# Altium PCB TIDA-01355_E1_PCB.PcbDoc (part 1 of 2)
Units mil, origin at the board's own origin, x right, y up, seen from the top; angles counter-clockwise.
Board outline 2150 x 1600 mil, 4 copper layers (Top Layer, GND, PWR, Bottom Layer), stack 59.906 mil thick; 85 components, 55 nets, 272 pads, 126 vias.
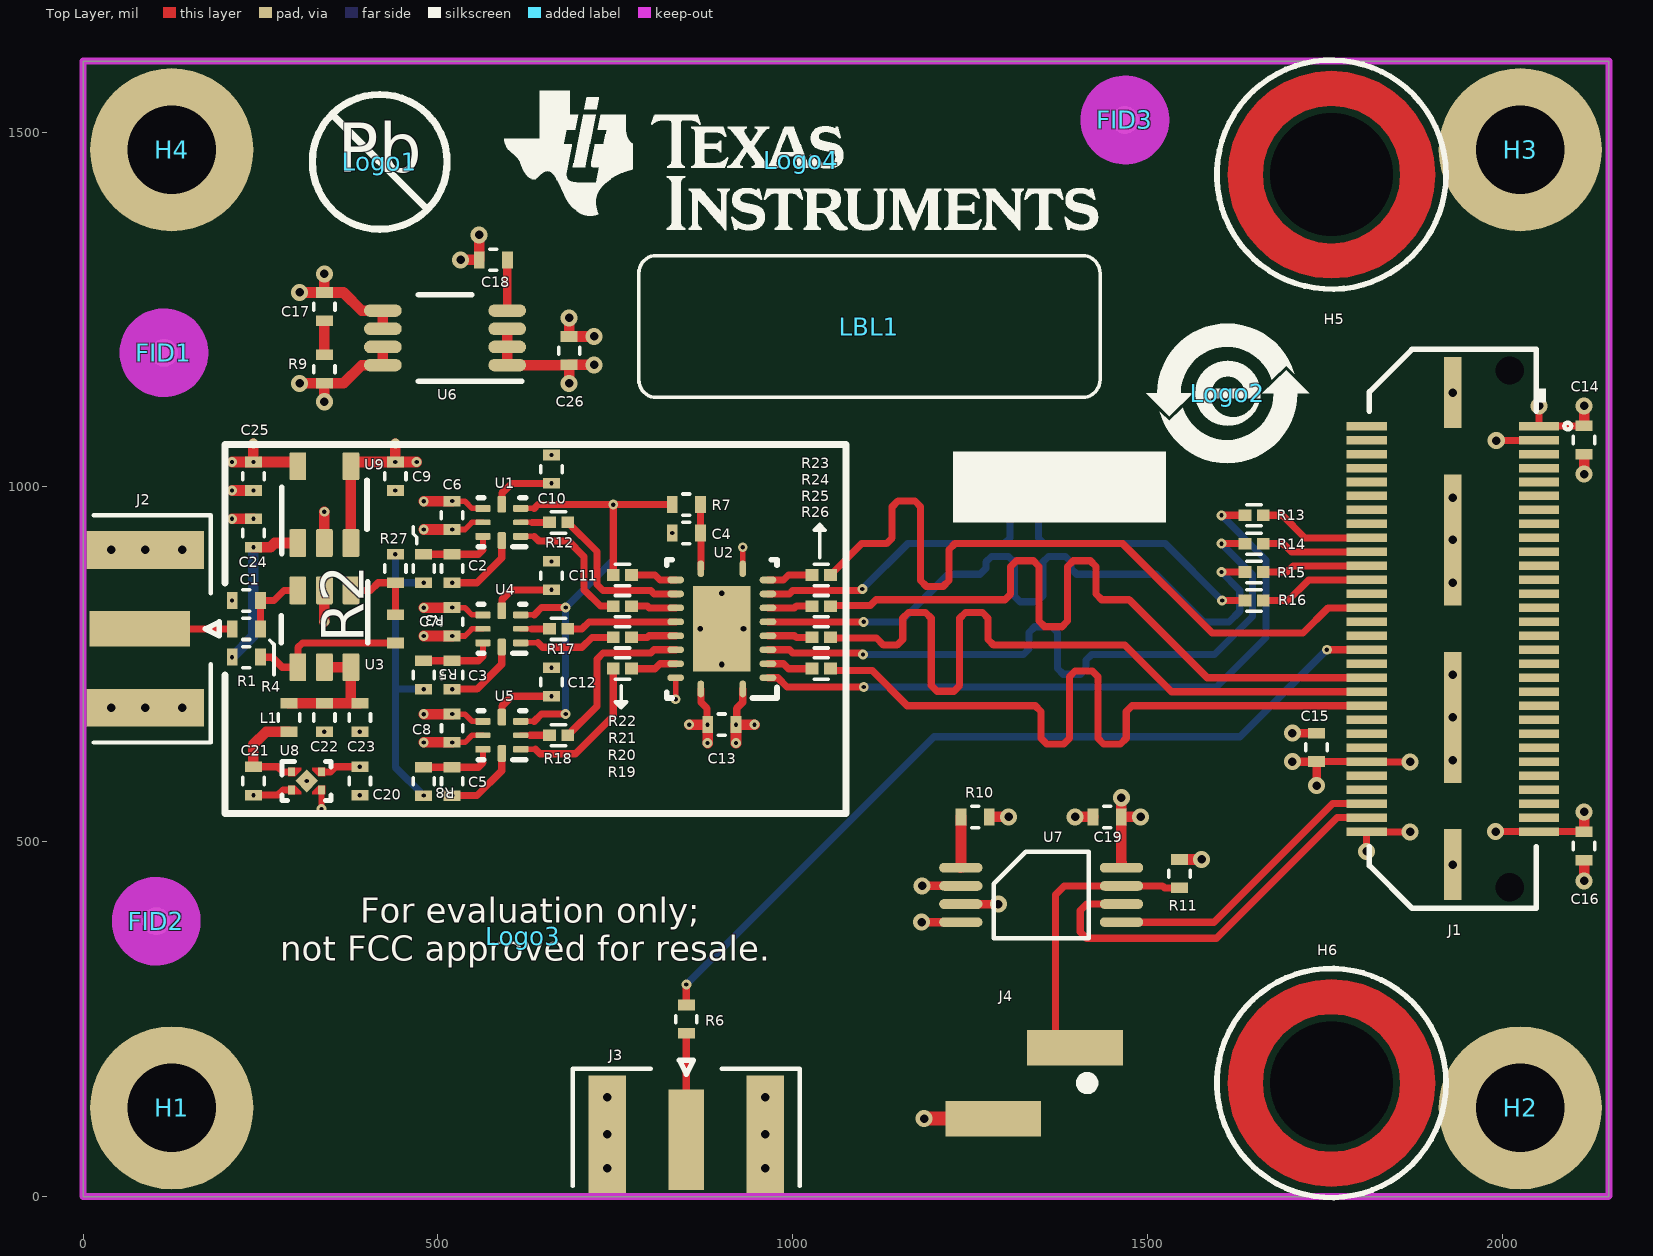
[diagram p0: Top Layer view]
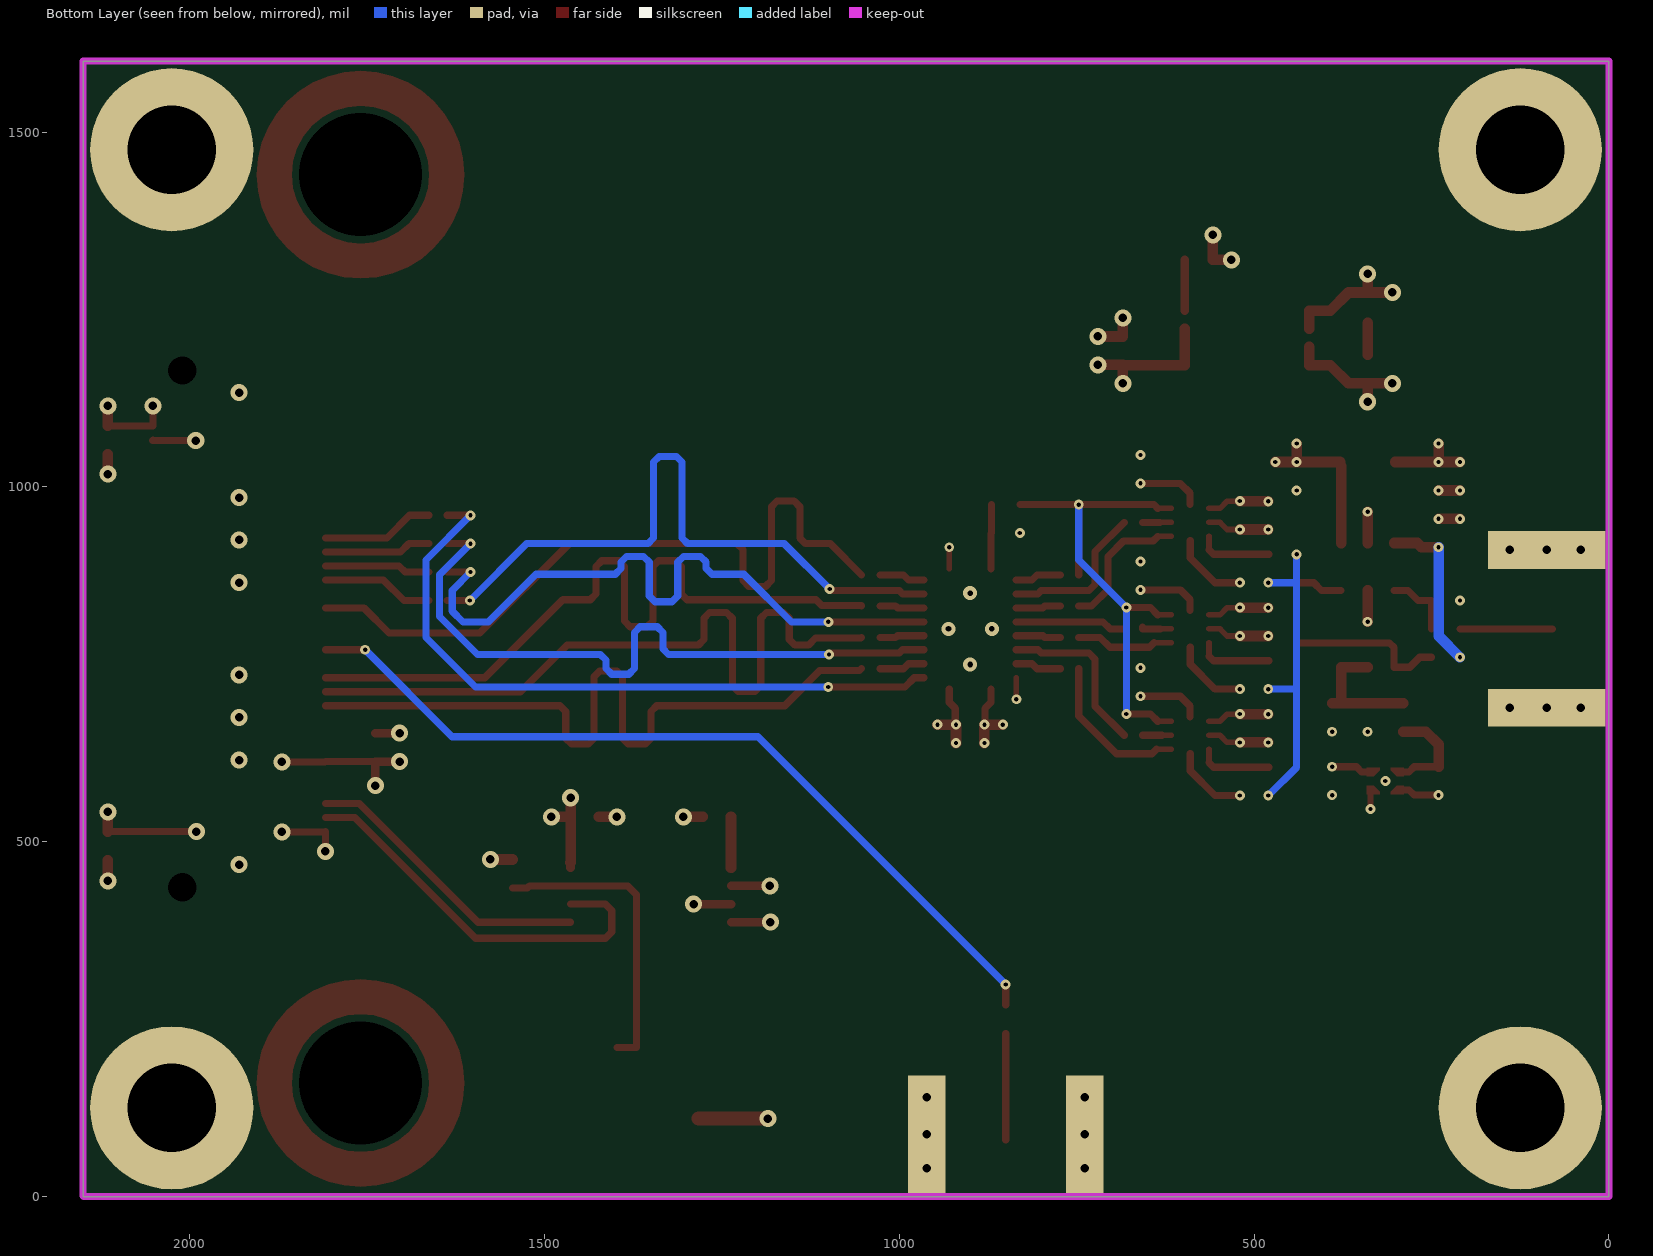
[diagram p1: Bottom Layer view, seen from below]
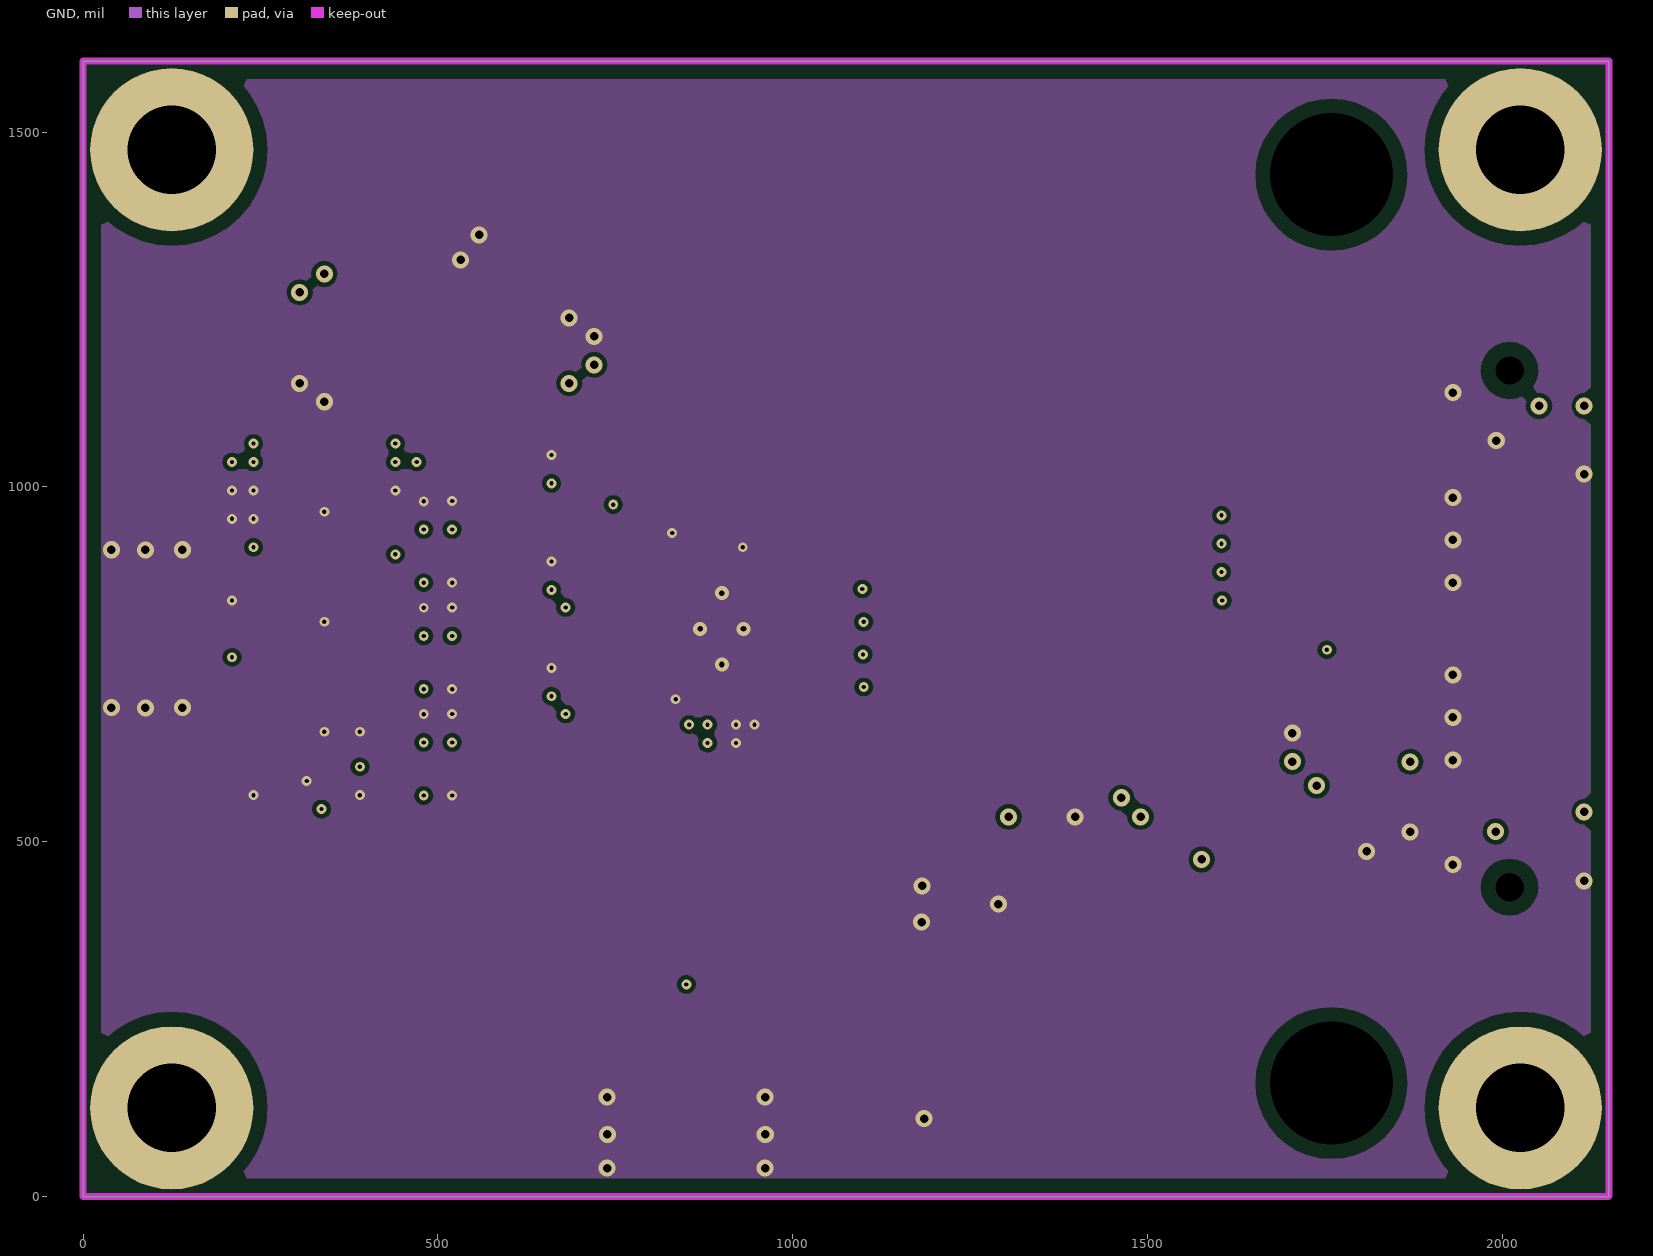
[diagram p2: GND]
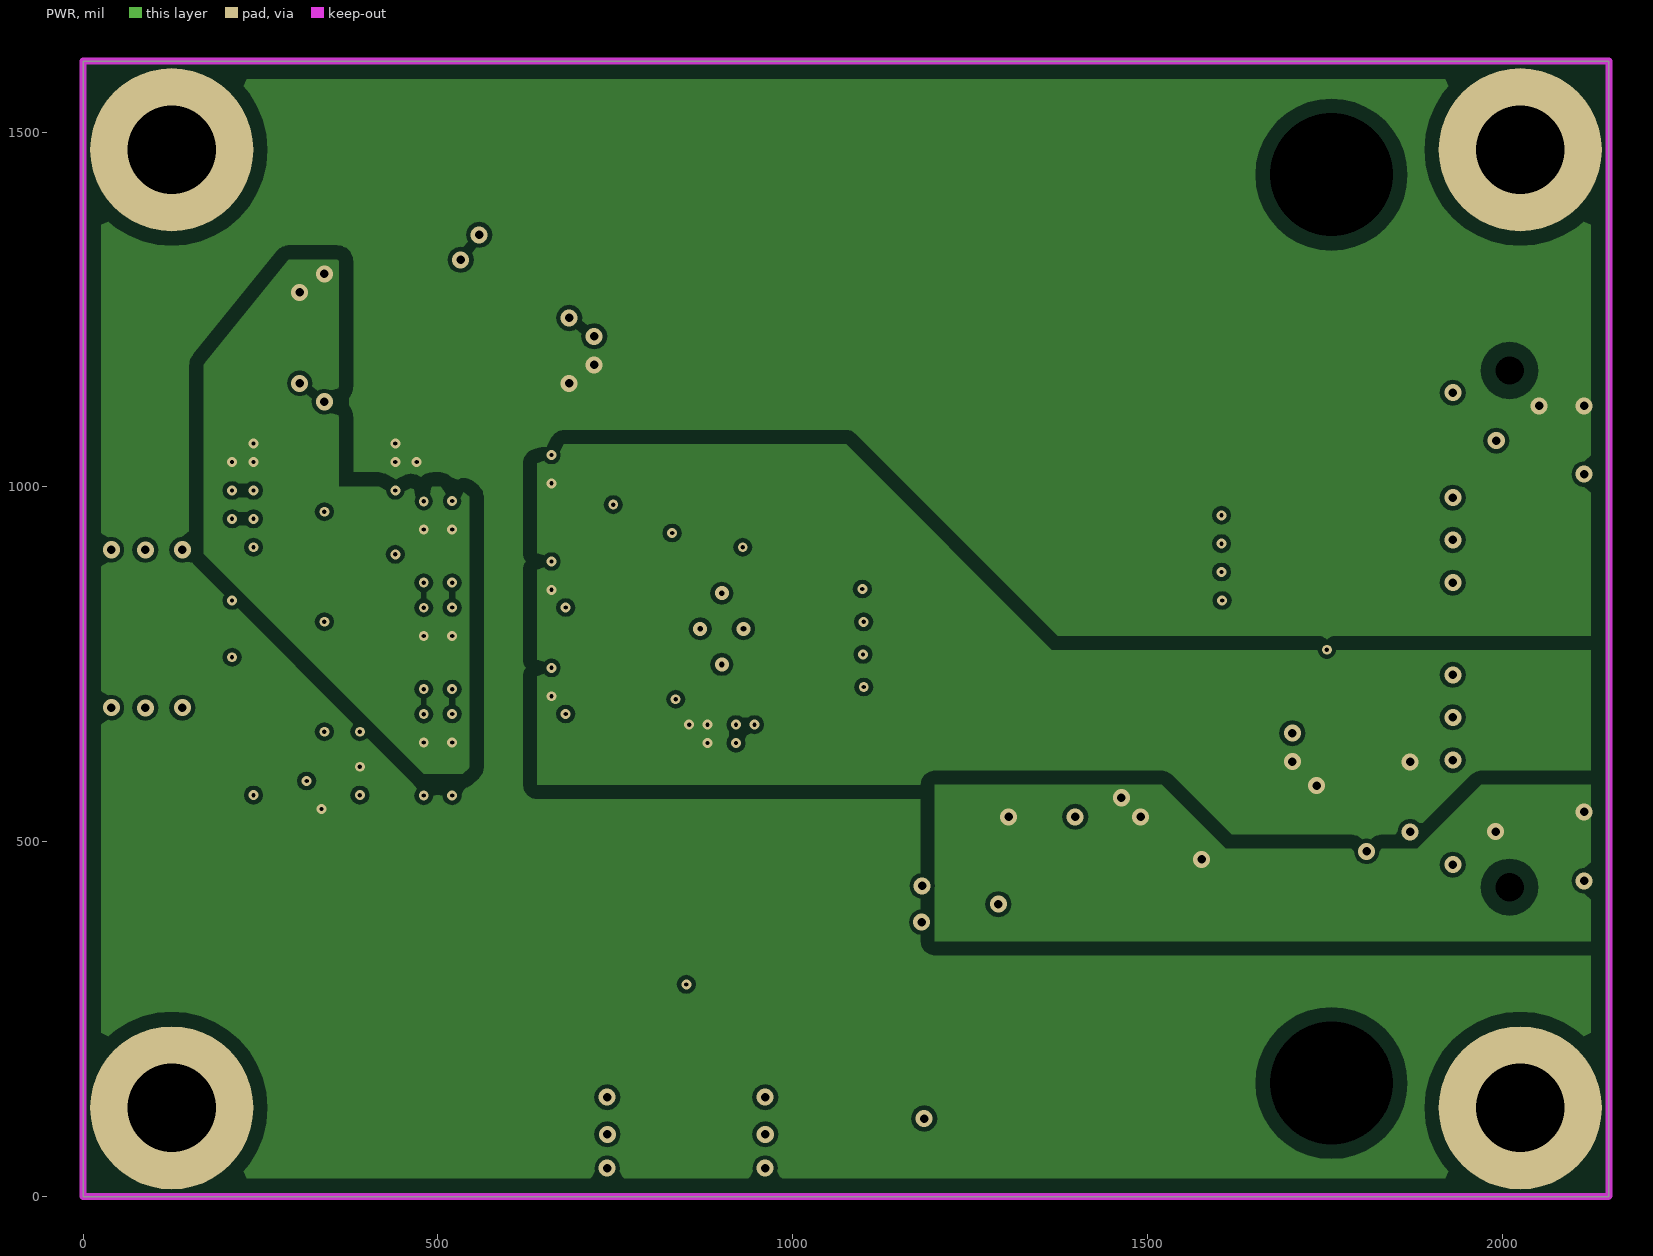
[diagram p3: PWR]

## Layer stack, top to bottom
Top Solder: solder mask 0.4, Solder Resist, Dk 3.5
Top Layer: signal copper 2.59
Dielectric1: core 6.3, FR-4, Dk 4.2
GND: signal copper 1.378
Dielectric 3: prepreg 39.37, Dk 4.2
PWR: signal copper 1.378
Dielectric 2: core 6.3, FR-4, Dk 4.2
Bottom Layer: signal copper 2.59
Bottom Solder: solder mask 0.4, Solder Resist, Dk 3.5

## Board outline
0,0 0,1600 2150,1600 2150,0

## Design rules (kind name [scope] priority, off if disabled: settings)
AcuteAngle [All] p1: minimum=4.50000000000000E+0001 checktracksonly=FALSE
AssemblyTestPointUsage [All] p1: valid=2
BoardOutlineClearance BoardOutlineClearance_MountingHoles [OnCopper and InComponentClass('Mounting Holes')] p1: gap=40
BoardOutlineClearance BoardOutlineClearance_Poly [OnCopper and IsPoly] p2: gap=25
BoardOutlineClearance [OnCopper and Not InComponentClass('Logo') and not InComponentClass('FiducialMark') and not InRegion(1000,500,4000,800) and not InPoly] p3: gap=75
Clearance Clearance_Keepouts [((IsTrack Or IsArc) And Not InPoly) And IsFree and IsKeepOut vs ((IsTrack Or IsArc) And Not InPoly) And IsFree and IsKeepOut] p1: gap=0
Clearance Clearance_Poly [InPolygon] p2: gap=20 except(6: Via-Poly; 8: SMDPad-Poly; 10: Arc-Poly Track-Poly)
Clearance [All] p3: gap=7.5
ComponentClearance ComponentClearance_MountingHoles_FiducialMarks [InComponentClass('Mounting Holes') vs InComponentClass('FiducialMark')] p1: gap=10 collisioncheckmode=3 verticalgap=10 showdistances=FALSE
ComponentClearance ComponentClearance_Shunt [InComponentClass('Header') vs InComponentClass('Shunt')] p2: gap=0 collisioncheckmode=3 verticalgap=0 showdistances=FALSE
ComponentClearance ComponentClearance_Logo [InComponentClass('Logo')] p3: gap=10 collisioncheckmode=3 verticalgap=10 showdistances=FALSE
ComponentClearance ComponentClearance_ScrewToNut [(HasFootprint('NY PMS 440 0025 PH')) vs (HasFootprint('Keystone_1902C'))] p4: gap=5 collisioncheckmode=3 verticalgap=10 showdistances=FALSE
ComponentClearance ComponentClearance_MountingHoles [InComponentClass('Mounting Holes')] p5: gap=100 collisioncheckmode=3 verticalgap=100000 showdistances=FALSE
ComponentClearance ComponentClearance_SmallPassives [HasFootprint('0201*') or HasFootprint('0402*') or HasFootprint('0508') or HasFootprint('0603*') or HasFootprint('0612') or HasFootprint('0805*') or HasFootprint('0815*') or HasFootprint('0830*') or HasFootprint('1206*') or HasFootprint('1210*') or HasFootprint('1808*') or HasFootprint('1812*') or HasFootprint('1825*') or HasFootprint('2010*') or HasFootprint('2220*') or HasFootprint('2225*') or HasFootprint('2512*') or HasFootprint('2728*') or HasFootprint('3518*') vs HasFootprint('0201*') or HasFootprint('0402*') or HasFootprint('0508') or HasFootprint('0603*') or HasFootprint('0612') or HasFootprint('0805*') or HasFootprint('0815*') or HasFootprint('0830*') or HasFootprint('1206*') or HasFootprint('1210*') or HasFootprint('1808*') or HasFootprint('1812*') or HasFootprint('1825*') or HasFootprint('2010*') or HasFootprint('2220*') or HasFootprint('2225*') or HasFootprint('2512*') or HasFootprint('2728*') or HasFootprint('3518*')] p6: gap=12 collisioncheckmode=3 verticalgap=10 showdistances=FALSE
ComponentClearance ComponentClearance_THtoSMT [IsThruComponent vs IsSMTComponent] p7: gap=20 collisioncheckmode=3 verticalgap=15 showdistances=FALSE
ComponentClearance ComponentClearance_THtoTH [IsThruComponent vs IsThruComponent] p8: gap=20 collisioncheckmode=3 verticalgap=20 showdistances=FALSE
ComponentClearance [All] p9: gap=20 collisioncheckmode=3 verticalgap=10 showdistances=FALSE
DiffPairsRouting [All] p1: maxlimit=100 minlimit=10 mostfreqgap=10 toplayer_minwidth=15 toplayer_maxwidth=15 toplayer_prefwidth=15 midlayer1_minwidth=15 midlayer1_maxwidth=15 midlayer1_prefwidth=15 midlayer2_minwidth=15 midlayer2_maxwidth=15 midlayer2_prefwidth=15 bottomlayer_minwidth=15 bottomlayer_maxwidth=15 bottomlayer_prefwidth=15 maxuncoupledlength=1000
FabricationTestPointUsage TestPointUsage [All] p1: valid=2 allowmultiple=FALSE
FabricationTestpoint Testpoint [All] p1: side=3 testpointundercomponent=TRUE minsize=40 maxsize=100 preferedsize=60 minholesize=0 maxholesize=40 preferedholesize=32 testpointgrid=1 allowsidetop=TRUE allowsidebottom=TRUE usegrid=TRUE gridtolerance=0.01
FanoutControl Fanout_LCC [IsLCC] p1: bgadir=Out bgaviamode=Centered fanoutstyle=Auto fanoutdirection=Alternating viagrid=1 // Fanout_LCC (Default Rule)
FanoutControl Fanout_BGA [IsBGA] p2: bgadir=Out bgaviamode=Centered fanoutstyle=Auto fanoutdirection=Alternating viagrid=1 // Fanout_BGA (Default Rule)
FanoutControl Fanout_Default [All] p4: bgadir=Out bgaviamode=Centered fanoutstyle=Auto fanoutdirection=Alternating viagrid=1 // Fanout_Default (Default Rule)
FanoutControl Fanout_Small [(CompPinCount < 5)] p5: bgadir=Out bgaviamode=Centered fanoutstyle=Auto fanoutdirection=OutThenIn viagrid=1 // Fanout_Small (Default Rule)
HoleSize [All] p1: absolutevalues=TRUE maxlimit=251 minlimit=6 maxpercent=80.000 minpercent=20.000
MinimumAnnularRing MinimumAnnularRing_ThermalPadVias [IsVia and InAnyComponent] p1: minimumring=3
MinimumAnnularRing [All] p2: minimumring=3
MinimumSolderMaskSliver MinimumSolderMaskSliver_Logo [InComponentClass('Logo') vs InComponentClass('Logo')] p1: minsoldermaskwidth=0.7
MinimumSolderMaskSliver [All] p2: minsoldermaskwidth=3
PlaneConnect [All] p1: planeconnectstyle=Direct reliefexpansion=10 reliefentries=4 reliefconductorwidth=10 reliefairgap=10
PolygonConnect [All] p1: connectstyle=Direct reliefconductorwidth=10 reliefentries=4 polygonreliefangle="90 Angle" airgapwidth=10
RoutingVias ThermalPadVias [IsVia and InAnyComponent] p1: holewidth=7.87 width=19.68 viastyle="Through Hole" minholewidth=7.87 minwidth=19.68 maxholewidth=12.99 maxwidth=23.62
RoutingVias [All] p2: holewidth=12 width=24 viastyle="Through Hole" minholewidth=6 minwidth=14 maxholewidth=16 maxwidth=32
SilkToBoardRegionClearance [Not ((IsComment or IsDesignator) And (Hide <> 'False')) and not InRegion(1000,500,4000,800)] p1:
SilkToSilkClearance SilkToSilkClearance_Pb-FreeLogo [(HasFootprint('Pb-Free_Overlay_Medium') OR HasFootprint('Pb-Free_Overlay_Small')) vs (HasFootprint('Pb-Free_Overlay_Medium') OR HasFootprint('Pb-Free_Overlay_Small'))] p1: silktosilkclearance=0
SilkToSilkClearance [All] p2: silktosilkclearance=0
SilkToSolderMaskClearance SilkToComponentPadClearance [IsPad and InAnycomponent] p1: minsilkscreentomaskgap=0 clearancetoexposedcopper=TRUE
SilkToSolderMaskClearance "Silk to Solder Mask Opening" [All] p2: minsilkscreentomaskgap=0 clearancetoexposedcopper=FALSE
SolderMaskExpansion [All] p1: expansion=1.97
Width Width_PWR [InNetClass('PWR')] p1: maxlimit=30 minlimit=6 preferedwidth=15
Width [All] p2: maxlimit=30 minlimit=6 preferedwidth=10.06 checkconnectedcopper=TRUE
15 further rules are at their usual default settings.

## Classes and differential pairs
component class Header: J4
component class TIDA-01355_E1_AFE_Circuit: C1 C2 C3 C4 C5 C6 C7 C8 C9 C10 C11 C12 C13 C14 C15 C16 C17 C18 C19 C20 C21 C22 C23 C24 C25 C26 J1 J2 J3 J4 L1 R1 R2 R3 R4 R5 R6 R7 R8 R9 R10 R11 R12 R13 R14 R15 R16 R17 R18 R19 R20 R21 R22 R23 R24 R25 R26 R27 U1 U2 U3 U4 U5 U6 U7 U8 U9
component class Logo: Logo4
component class TIDA-01355_E1_EVM_Hardware: FID1 FID2 FID3 H1 H2 H3 H4 H5 H6 LBL1 Logo1 Logo2 Logo3 Logo4 ZZ1 ZZ2 ZZ3 ZZ4
component class FiducialMark: FID1 FID2 FID3
component class AssemblyNote: ZZ1 ZZ2 ZZ3 ZZ4
component class Label: LBL1
net class AVDD: AVDD
net class EVM_DVDD: EVM_DVDD
net class EVM_REG_5V5: EVM_REG_5V5
net class EVM_ID_PWR: EVM_ID_PWR

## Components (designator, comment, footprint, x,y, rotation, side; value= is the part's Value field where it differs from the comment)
C1 "GRM1555C1H100JA01D" 0402S 230,840 r180 top
C2 "GRM1555C1E111JA01D" 0402S 520,885 r270 top
C3 "GRM1555C1E111JA01D" 0402S 520,735 r270 top
C4 "GRM1555C1E510JA01D" 0402S 850,935 r180 top
C5 "GRM1555C1E111JA01D" 0402S 520,585 r270 top
C6 "C1005X5R1C225K050BC" 0402S 520,960 r90 top
C7 "C1005X5R1C225K050BC" 0402S 520,810 r90 top
C8 "C1005X5R1C225K050BC" 0402S 520,660 r90 top
C9 "885012205037" 0402S 440,1015 r270 top
C10 "885012205037" 0402S 660,1025 r90 top
C11 "885012205037" 0402S 660,875 r90 top
C12 "885012205037" 0402S 660,725 r90 top
C13 "885012205037" 0402S 900,665 r0 top
C14 "CL05A106MP5NUNC" 0402S 2115,1066 r270 top
C15 "CL05A106MP5NUNC" 0402S 1738,633 r90 top
C16 "CL05A106MP5NUNC" 0402S 2115,494 r270 top
C17 "LDK105EBJ226MV-F" 0402_080S 340,1254 r270 top
C18 "GCM155C71A105KE38D" 0402_070 578,1320 r180 top
C19 "885012205037" 0402S 1443,535 r180 top
C20 "CL05A106MP5NUNC" 0402S 390,585.67 r270 top
C21 "CL05A106MP5NUNC" 0402S 240,585.67 r270 top
C22 "CL05A106MP5NUNC" 0402S 340,675 r270 top
C23 "885012205037" 0402S 390,675 r270 top
C24 "CL05A106MP5NUNC" 0402S 240,935 r90 top
C25 "CL05A106MP5NUNC" 0402S 240,1015 r270 top
C26 "885012205037" 0402S 685,1192 r90 top
FID1 "Fiducial" Fiducial10-30 114,1189 r0 top
FID2 "Fiducial" Fiducial10-30 103,388 r0 top
FID3 "Fiducial" Fiducial10-30 1468,1517 r0 top
H1 "PMSSS 440 0025 PH" B_F_PMSSS4400025PH 125,125 r0 top locked
H2 "PMSSS 440 0025 PH" B_F_PMSSS4400025PH 2025,125 r0 top locked
H3 "PMSSS 440 0025 PH" B_F_PMSSS4400025PH 2025,1475 r0 top locked
H4 "PMSSS 440 0025 PH" B_F_PMSSS4400025PH 125,1475 r0 top locked
H5 "9774050360R" Wurth_WA-SMSI 1759,1440 r0 top
H6 "9774050360R" Wurth_WA-SMSI 1759,160 r0 top
J1 "QTH-030-01-L-D-A" Samtec_QTH-030-01-x-D-A 1930,800 r270 top locked
J2 "SMA-J-P-H-ST-EM1" SAMTEC_SMA-J-P-H-ST-EM1 5,800 r270 top
J3 "SMA-J-P-H-ST-EM1" SAMTEC_SMA-J-P-H-ST-EM1 850,5 r0 top
J4 "TSM-102-01-L-SV" Samtec_TSM-102-01-L-SV 1340,160 r270 top
L1 "BLM15AX102SN1D" 0402S 290,675 r90 top
LBL1 "Size: 0.65\" x 0.20 \"" Label_650x200 1108,1226 r0 top
Logo1 "Pb-Free Symbol" Pb-Free_Overlay_Medium 418,1458 r0 top
Logo2 "China RoHS" ChinaRoHS_5mm 1613,1132 r0 top
Logo3 "FCC disclaimer" FCC_disclaimer_stacked 620,367 r0 top
Logo4 "Texas Instruments" TI_Stacked_Overlay_Small 1012,1460 r0 top
R1 "PCF0402-12-3K32BT1" 0402S 230,760 r0 top
R2 "CRCW04020000Z0ED" 0402S 440,800 r90 top
R3 "CRCW04020000Z0ED" 0402S 480,885 r270 top
R4 "CRCW0402150RJNED" 0402S 230,800 r0 top
R5 "CRCW04020000Z0ED" 0402S 480,735 r270 top
R6 "CRCW040210R0FKED" 0402S 850,250 r90 top
R7 "CRCW040220R0FKED" 0402S 850,975 r0 top
R8 "CRCW04020000Z0ED" 0402S 480,585 r270 top
R9 "CRCW04020000Z0ED" 0402S 340,1166 r90 top
R10 "ERJ-2GEJ103X" 0402S 1257,535 r0 top
R11 "ERJ-2GEJ103X" 0402S 1545,455 r90 top
R12 "ERJ-1GEF49R9C" 0201 670,950 r0 top
R13 "ERJ-1GEF49R9C" 0201 1650,960 r0 top
R14 "ERJ-1GEF49R9C" 0201 1650,920 r0 top
R15 "ERJ-1GEF49R9C" 0201 1650,880 r0 top
R16 "ERJ-1GEF49R9C" 0201 1650,840 r0 top
R17 "ERJ-1GEF49R9C" 0201 670,800 r0 top
R18 "ERJ-1GEF49R9C" 0201 670,650 r0 top
R19 "ERJ-1GEF49R9C" 0201 760,744 r0 top
R20 "ERJ-1GEF49R9C" 0201 760,788 r0 top
R21 "ERJ-1GEF49R9C" 0201 760,832 r0 top
R22 "ERJ-1GEF49R9C" 0201 760,876 r0 top
R23 "ERJ-1GEF49R9C" 0201 1040,876 r180 top
R24 "ERJ-1GEF49R9C" 0201 1040,832 r180 top
R25 "ERJ-1GEF49R9C" 0201 1040,788 r180 top
R26 "ERJ-1GEF49R9C" 0201 1040,744 r180 top
R27 "ERJ-2RKF33R0X" 0402S 440,885 r90 top
U1 "ADS7056IRUGR" RUG0008A 590,950 r180 top
U2 "SN74AUCH244RGYR" RGY0020A 900,800 r180 top
U3 "OPA836IDBVR" DBV0006A_N 340,800 r270 top
U4 "ADS7056IRUGR" RUG0008A 590,800 r180 top
U5 "ADS7056IRUGR" RUG0008A 590,650 r180 top
U6 "REF6030IDGKR" DGK0008A_N 510,1210 r180 top
U7 "BR24G32FVT-3AGE2" TSOP65P640X120-8N 1350,425 r0 top
U8 "LP5907SNX-4.5/NOPB" DQN0004A 315,585.67 r0 top
U9 "REF2033AIDDCR" DDC0005A_N 340,975 r90 top
ZZ1 "This Assembly Note is for PCB labels only" AssemblyNoteLabel 185,3938 r0 top
ZZ2 "These assemblies are ESD sensitive, ESD precautions shall be observed." AssemblyNote 185,3829.11 r0 top
ZZ3 "These assemblies must be clean and free from flux and all contaminants. Use of no clean flux is not acceptable." AssemblyNote 185,3740.56 r0 top
ZZ4 "These assemblies must comply with workmanship standards IPC-A-610 Class 2, unless otherwise specified." AssemblyNote 185,3652 r0 top

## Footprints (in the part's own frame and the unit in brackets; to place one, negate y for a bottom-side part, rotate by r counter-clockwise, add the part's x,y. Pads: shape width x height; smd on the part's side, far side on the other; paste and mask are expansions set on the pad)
0201 [mm] "Data from Kemet datasheet CC101_COM dated 7/28/11"
  rect 0.46x0.42 smd mask+0.048: 1(-0.33,0) 2(0.33,0)
  silkscreen extent -0.25,-0.38 0.25,0.38, body extent -0.31,-0.16 0.31,0.16, height 0.26
0402_070 [mil] "SMD, 2-Leads, Body 1.2x0.7mm, Height 0.7mm"
  rect 15x24 smd: 1(-20,0) 2(20,0)
  silkscreen extent -5,-15 5,15, body extent -24,-14 24,14, height 28
0402_080S [mil] "Based on C0402S footprint from PADS legacy"
  rect 15x24 smd: 1(-20,0) 2(20,0)
  silkscreen extent -5,-15 5,15, body extent -26,-16 26,16, height 31
0402S [mil] "Based on C0402S footprint from PADS legacy"
  rect 15x24 smd: 1(-20,0) 2(20,0)
  silkscreen extent -5,-15 5,15, body extent -22,-12 22,12, height 24
AssemblyNote [mil] "Assembly Note"
AssemblyNoteLabel [mil] "Assembly Note for PCB Labels"
B_F_PMSSS4400025PH [mil] "MACHINE SCREW PAN PHILLIPS 4-40"
  round 230 hole 125: 1(0,0)
  body extent -109,-109 110,110, height 79
ChinaRoHS_5mm [mil] "Minimum height for China RoHS symbol"
  silkscreen extent -115,-99 114,98
DBV0006A_N [mm] "SOT23, 6-Leads, Body 2.9x1.6mm, Pitch 0.95mm, Lead Span 2.8mm, IPC Medium Density"
  rrect17% 1x0.6 smd: 1(-1.375,0.95) 2(-1.375,0) 3(-1.375,-0.95) 4(1.375,-0.95) 5(1.375,0) 6(1.375,0.95)
  silkscreen extent -1.68,-1.55 0.5,1.55, body extent -1.42,-1.46 1.42,1.46, height 1.12
DDC0005A_N [mm]
  rrect17% 1x0.6 smd: 1(-1.375,0.95) 2(-1.375,0) 3(-1.375,-0.95) 4(1.375,-0.95) 5(1.375,0.95)
  silkscreen extent -1.75,-1.52 0.88,1.53, body extent -1.41,-1.45 1.41,1.45, height 1.1
DGK0008A_N [mm] "TSOP, 8-Leads, Body 3x3mm, Pitch 0.65mm, IPC Medium Density"
  oval 1.35x0.45 smd: 1(-2.225,0.975) 2(-2.225,0.325) 3(-2.225,-0.325) 4(-2.225,-0.975) 5(2.225,-0.975) 6(2.225,-0.325) 7(2.225,0.325) 8(2.225,0.975)
  silkscreen extent -2.75,-1.55 0.95,1.55, body extent -2.45,-1.5 2.45,1.5, height 0.96
DQN0004A [mm] "SON, 0.65mm pitch"
  rect 0.25x0.31 smd paste-1 mask-0.31: 1(-0.535,0.325) 2(-0.535,-0.325) 3(0.535,-0.325) 4(0.535,0.325)
  rect 0.58x0.58 smd rot 45 paste-0.065 mask-0.05: 5(0,0)
  Top Layer region: -0.66,-0.48 -0.2,-0.48 -0.2,-0.379 -0.409,-0.17 -0.66,-0.17
  Top Layer region: 0.66,-0.48 0.2,-0.48 0.2,-0.379 0.409,-0.17 0.66,-0.17
  Top Layer region: 0.66,0.48 0.2,0.48 0.2,0.379 0.409,0.17 0.66,0.17
  Top Layer region: -0.66,0.48 -0.2,0.48 -0.2,0.379 -0.409,0.17 -0.66,0.17
  silkscreen extent -0.88,-0.7 0.88,0.7, body extent -0.53,-0.53 0.53,0.53, height 0.42
FCC_disclaimer_stacked [mil]
Fiducial10-30 [mm]
  round 1 smd mask+1: 1(0,0)
  Top Layer keep-out circle w1.678: c0,0 r0.75
Label_650x200 [mil] "Thermal Transfer Label"
  silkscreen extent -325,-100 325,100, body extent -325,-100 325,100, height 1
Pb-Free_Overlay_Medium [mil]
  silkscreen extent -95,-95 95,95
RGY0020A [mm] "QFN, 20-Leads, Body 4.5x3.5mm, Pitch 0.5mm, Thermal Pad 3.05x2.05mm, TI Recommended"
  oval 0.24x0.6 smd: 1(-0.75,2.15) 10(-0.75,-2.15) 11(0.75,-2.15) 20(0.75,2.15)
  oval 0.6x0.24 smd: 2(-1.65,1.75) 3(-1.65,1.25) 4(-1.65,0.75) 5(-1.65,0.25) 6(-1.65,-0.25) 7(-1.65,-0.75) 8(-1.65,-1.25) 9(-1.65,-1.75) 12(1.65,-1.75) 13(1.65,-1.25) 14(1.65,-0.75) 15(1.65,-0.25) 16(1.65,0.25) 17(1.65,0.75) 18(1.65,1.25) 19(1.65,1.75)
  rect 2.05x3.05 smd paste-1.025: 21(0,0)
  silkscreen extent -1.97,-2.47 1.97,2.47, body extent -1.75,-2.25 1.75,2.25, height 1
RUG0008A [mm] "QFN, 8-Leads, Body 1.5x1.5mm, Pitch 0.5mm, TI Recommended"
  rrect40% 0.55x0.25 smd: 1(-0.675,0.5) 3(-0.675,-0.5) 5(0.675,-0.5) 7(0.675,0.5)
  rrect50% 0.55x0.2 smd: 2(-0.675,0) 6(0.675,0)
  rrect33% 0.3x0.6 smd: 4(0,-0.65) 8(0,0.65)
  silkscreen extent -0.85,-0.87 0.85,0.87, body extent -0.78,-0.78 0.77,0.77, height 0.41
Samtec_QTH-030-01-x-D-A [mil] "Header (Shrouded), 19.7mil, 30x2, SMT"
  rect 12x57 smd: 1(-285.7,121.5) 2(-285.7,-121.5) 3(-266,121.5) 4(-266,-121.5) 5(-246.3,121.5) 6(-246.3,-121.5) 7(-226.6,121.5) 8(-226.6,-121.5) 9(-206.9,121.5) 10(-206.9,-121.5) 11(-187.2,121.5) 12(-187.2,-121.5) 13(-167.5,121.5) 14(-167.5,-121.5) 15(-147.8,121.5) 16(-147.8,-121.5) 17(-128.1,121.5) 18(-128.1,-121.5) 19(-108.4,121.5) 20(-108.4,-121.5) 21(-88.7,121.5) 22(-88.7,-121.5) 23(-69,121.5) 24(-69,-121.5) 25(-49.3,121.5) 26(-49.3,-121.5) 27(-29.6,121.5) 28(-29.6,-121.5) 29(-9.9,121.5) 30(-9.9,-121.5) 31(9.8,121.5) 32(9.8,-121.5) 33(29.5,121.5) 34(29.5,-121.5) 35(49.2,121.5) 36(49.2,-121.5) 37(68.9,121.5) 38(68.9,-121.5) 39(88.6,121.5) 40(88.6,-121.5) 41(108.3,121.5) 42(108.3,-121.5) 43(128,121.5) 44(128,-121.5) 45(147.7,121.5) 46(147.7,-121.5) 47(167.4,121.5) 48(167.4,-121.5) 49(187.1,121.5) 50(187.1,-121.5) 51(206.8,121.5) 52(206.8,-121.5) 53(226.5,121.5) 54(226.5,-121.5) 55(246.2,121.5) 56(246.2,-121.5) 57(265.9,121.5) 58(265.9,-121.5) 59(285.6,121.5) 60(285.6,-121.5)
  round 0 hole 40 unplated mask+45: MH1(-364,80) MH2(364,80)
  rect 100x25 smd: MP1(-332.7,0) MP4(332.3,0)
  rect 185x25 smd: MP2(-125.2,0) MP3(124.8,0)
  silkscreen extent -394,-118 394,131, body extent -394,-140 394,140, height 170
SAMTEC_SMA-J-P-H-ST-EM1 [mm] "SMA Jack, R/A, SMT"
  rect 1.27x3.6 smd: 1(0,1.9)
  rect 1.35x4.2 smd: 2(-2.825,2.1) 3(2.825,2.1)
  rect 1.35x4.2 smd far side: 4(-2.825,2.1) 5(2.825,2.1)
  silkscreen extent -4.06,0.25 4.06,4.75, body extent -3.17,-9.52 3.18,3.81, height 3.8
Samtec_TSM-102-01-L-SV [mm] "SAMTEC"
  rect 1.27x3.43 smd: 1(-1.27,1.46) 2(1.27,-1.46)
  silkscreen extent -0.2,1.7 0.2,2.1, body extent -2.53,-2.45 2.55,2.45, height 9.65
TI_Stacked_Overlay_Small [mil]
  silkscreen extent -418,-98 418,98
TSOP65P640X120-8N [mm] "TSOP, 8-Leads, Body 3.1x4.5mm (max), Pitch 0.65mm, IPC Medium Density"
  oval 1.55x0.35 smd mask+0.08: 1(-2.875,0.975) 2(-2.875,0.325) 3(-2.875,-0.325) 4(-2.875,-0.975) 5(2.875,-0.975) 6(2.875,-0.325) 7(2.875,0.325) 8(2.875,0.975)
  silkscreen extent -1.7,-1.55 1.7,1.55, body extent -2.25,-1.55 2.25,1.55, height 1.21
Wurth_WA-SMSI [mm] "ROUND STANDOFF M3 STEEL 5MM"
  round 0 hole 4.4 unplated mask+0.508: ""(0,0)
  Top Layer region: -3.711,0 -3.666,0.581 -3.53,1.147 -3.307,1.685 -3.003,2.182 -2.624,2.624 -2.182,3.003 -1.685,3.307 -1.147,3.53 -0.581,3.666 0,3.711 0.581,3.666 1.147,3.53 1.685,3.307 2.182,3.003 2.624,2.624 3.003,2.182 3.307,1.685 3.53,1.147 3.666,0.581 3.711,0 3.7,0 2.466,0 2.418,0.481 2.278,0.944 2.05,1.37 1.744,1.744 1.37,2.05 0.944,2.278 0.481,2.418 0,2.466 -0.481,2.418 -0.944,2.278 -1.37,2.05 -1.744,1.744 -2.05,1.37 -2.278,0.944 -2.418,0.481 -2.466,0 -2.454,0
  Top Layer region: -3.711,0 -3.666,-0.581 -3.53,-1.147 -3.307,-1.685 -3.003,-2.182 -2.624,-2.624 -2.182,-3.003 -1.685,-3.307 -1.147,-3.53 -0.581,-3.666 0,-3.711 0.581,-3.666 1.147,-3.53 1.685,-3.307 2.182,-3.003 2.624,-2.624 3.003,-2.182 3.307,-1.685 3.53,-1.147 3.666,-0.581 3.711,0 3.7,0 2.466,0 2.418,-0.481 2.278,-0.944 2.05,-1.37 1.744,-1.744 1.37,-2.05 0.944,-2.278 0.481,-2.418 0,-2.466 -0.481,-2.418 -0.944,-2.278 -1.37,-2.05 -1.744,-1.744 -2.05,-1.37 -2.278,-0.944 -2.418,-0.481 -2.466,0 -2.454,0
  silkscreen extent -4.1,-4.1 4.1,4.1, body extent -2.99,-2.98 2.99,3, height 5

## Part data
C1: "CAP, CERM, 10 pF, 50 V, +/- 5%, C0G/NP0, 0402"
C2 C3 C5: "CAP, CERM, 110 pF, 25 V, +/- 5%, C0G/NP0, 0402"
C4: "CAP, CERM, 51 pF, 25 V, +/- 5%, C0G/NP0, 0402"
C6 C7 C8: "CAP, CERM, 2.2 µF, 16 V, +/- 10%, X5R, 0402"
C9 C10 C11 C12 C13 C19 C23 C26: "CAP, CERM, 0.1 µF, 16 V, +/- 10%, X7R, 0402"
C14 C15 C16 C20 C21 C22 C24 C25: "CAP, CERM, 10 µF, 10 V, +/- 20%, X5R, 0402"
C17: "CAP, CERM, 22 µF, 10 V, +/- 20%, X5R, 0402"
C18: "CAP, CERM, 1 µF, 10 V, +/- 10%, X7S, AEC-Q200 Grade 1, 0402"
FID1 FID2 FID3: "Fiducial mark.  There is nothing to buy or mount."
H1 H2 H3 H4: "MACHINE SCREW PAN PHILLIPS 4-40"
H5 H6: "ROUND STANDOFF M3 STEEL 5MM"
J1: "Header(Shrouded), 19.7mil, 30x2, Gold, SMT"
J2 J3: "SMA Jack, 50 Ohm, Gold, R/A, SMT"
J4: "Header, 100mil, 2x1, Gold with Tin Tail, SMT"
L1: "Ferrite Bead, 1000 ohm @ 100 MHz, 0.35 A, 0402"
LBL1: library part THT-14-423-10, "Thermal Transfer Printable Labels, 0.650\" W x 0.200\" H - 10,000 per roll"
Logo1: library part Pb-Free
Logo2: library part RoHS_China, "China RoHS Symbol"
Logo3: library part FCC_disclaimer, "FCC_disclaimer"
Logo4: library part TI_Logo, "Texas Instrument Corporate Signature"
R1: "RES, 3.32 k, 0.1%, 0.063 W, 0402"
R2 R3 R5 R8 R9: "RES, 0, 5%, 0.063 W, 0402"
R4: "RES, 150, 5%, 0.063 W, 0402"
R6: "RES, 10.0, 1%, 0.063 W, 0402"
R7: "RES, 20.0, 1%, 0.063 W, 0402"
R10 R11: "RES, 10 k, 5%, 0.1 W, AEC-Q200 Grade 0, 0402"
R12 R13 R14 R15 R16 R17 R18 R19 R20 R21 R22 R23 R24 R25 R26: "RES, 49.9, 1%, 0.05 W, 0201"
R27: "RES, 33.0, 1%, 0.1 W, 0402"
U1 U4 U5: "Ultra-Low Power, Ultra-Small Size, 14-Bit, 2.5-MSPS, SAR ADC, RUG0008A (X2QFN-8)"
U2: "Octal Buffer and Driver With 3-State Outputs, RGY0020A"
U3: "Very Low Power, Rail to Rail Out, Negative Rail In, VFB Operational Amplifier, 2.5 to 5.5 V, -40 to 125 degC, 6-pin SOT23 (DBV6), Green (RoHS & no Sb/Br)"
U6: "High-Precision Voltage Reference with Integrated High-Bandwidth Buffer, DGK0008A"
U7: "I2C BUS EEPROM (2-Wire), TSSOP-B8"
U8: "Ultra Low-Noise, 250-mA Linear Regulator for RF and Analog Circuits, DQN0004A"
U9: "Low-Drift, Low-Power, Dual-Output, VREF and VREF / 2 Voltage References, DDC0005A"
ZZ1: library part AssemblyNoteLabel
ZZ2 ZZ3 ZZ4: library part AssemblyNote

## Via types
v1: diameter 14, hole 6, Top Layer to Bottom Layer, 70 vias
v2: diameter 24, hole 12, Top Layer to Bottom Layer, 52 vias
v3: diameter 19.68, hole 7.87, Top Layer to Bottom Layer, 4 vias

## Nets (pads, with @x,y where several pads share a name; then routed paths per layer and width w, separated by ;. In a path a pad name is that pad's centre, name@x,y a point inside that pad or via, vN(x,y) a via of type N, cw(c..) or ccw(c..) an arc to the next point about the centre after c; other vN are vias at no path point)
+4V5A: C21.1 L1.1 U8.1 | length 145.7
  Top Layer w10: C21.1@240,605.67 274.33,605.67 281.54,598.46 U8.1@293.94,598.46
  Top Layer w15: C21.1@240,605.67 240,637 258,655 L1.1@290,655
ADC_CS_A: R21.1 U1.1 | length 198.4
  Top Layer w8: U1.1@616.57,930.32 635.68,930.32
  Top Layer w10.06: 635.68,930.32 642,924 683.62,924 706,901.62 706,855.07 729.07,832 R21.1@747.01,832
ADC_CS_B: R20.1 U4.1 | length 138.8
  Top Layer w8: U4.1@616.57,780.32 641.12,780.32
  Top Layer w10.06: 641.12,780.32 647.43,774 703,774 717,788 R20.1@747.01,788
ADC_CS_C: R19.1 U5.1 | length 222
  Top Layer w8: U5.1@616.57,630.32 637.68,630.32
  Top Layer w10.06: 637.68,630.32 644,624 694,624 747.01,677.01 R19.1@747.01,744
ADC_SCLK: R7.1 R22.1 U1.3 U4.3 U5.3 | length 772.8
  Top Layer w8: U5.3@616.57,669.69 635.69,669.69 ; U4.3@616.57,819.69 635.69,819.69 ; U1.3@616.57,969.69 635.69,969.69
  Top Layer w10.06: 635.69,669.69 646,680 v1(680,680) ; 635.69,819.69 646,830 v1(680,830) ; 635.69,969.69 641,975 v1(747.01,974.99) ; R22.1@747.01,876 v1(747.01,974.99) ; R7.1@830,975 v1(747.01,974.99)
  Bottom Layer w10.06: v1(680,680) v1(680,830) 747.01,897.01 v1(747.01,974.99)
ADC_SDO_A: R12.2 U2.13 | length 221.1
  Top Layer w10.06: R12.2@682.99,950 723.94,909.05 723.94,862.5 732.61,853.83 800,853.83 804.61,849.22 U2.13@835.04,849.22
ADC_SDO_B: R17.2 U2.15 | length 156.1
  Top Layer w10.06: R17.2@682.99,800 703,800 712.84,809.84 U2.15@835.04,809.84
ADC_SDO_C: R18.2 U2.17 | length 240.8
  Top Layer w10.06: R18.2@682.99,650 724,691.01 724,757.26 732.61,765.86 800,765.86 804.61,770.47 U2.17@835.04,770.47
AINP_A: C2.1 R3.1 U1.7 | length 106
  Top Layer w8: 563.43,911.43 U1.7@563.43,930.32
  Top Layer w10.06: R3.1@479,905 R3.1@480,905 C2.1@520,905 557,905 563.43,911.43
AINP_B: C3.1 R5.1 U4.7 | length 106
  Top Layer w8: 563.43,761.43 U4.7@563.43,780.32
  Top Layer w10.06: R5.1@479,755 R5.1@480,755 C3.1@520,755 557,755 563.43,761.43
AINP_C: C5.1 R8.1 U5.7 | length 106
  Top Layer w8: 563.43,611.43 U5.7@563.43,630.32
  Top Layer w10.06: R8.1@479,605 R8.1@480,605 C5.1@520,605 557,605 563.43,611.43
AVDD: C6.1 C7.1 C8.1 C17.1 C25.1 U1.6 U4.6 U5.6 U6.5 U6.6 U9.5 | length 559.3
  Top Layer w8: v1(520,640) 538,640 548,650 U5.6@563.43,650 ; v1(520,790) 538,790 548,800 U4.6@563.43,800 ; v1(520,940) 538,940 548,950 U1.6@563.43,950
  Top Layer w15: v1(210,1035) v1(240,1035) ; v1(240,1061) v1(240,1035) ; U9.5@301,1035 v1(240,1035) ; v2(305,1274.01) C17.1@340,1274 ; v2(340,1300.01) C17.1@340,1274 ; U6.6@422.4,1222.8 U6.5@422.4,1248.39 392.6,1248.39 366.99,1274.01 C17.1@340,1274 ; v1(480,640) v1(520,640) ; v1(480,790) v1(520,790) ; v1(480,940) v1(520,940)
AVDD_OPA+: C22.1 C23.1 L1.2 U3.5 U3.6 | length 186.6
  Top Layer w15: L1.2@290,695 C22.1@340,695 C23.1@390,695 ; U3.5@340,745.87 U3.6@377.4,745.87 377.4,696.65
CS_A: R15.1 U2.6 | length 966.1
  Top Layer w10.06: U2.6@964.96,809.84 v1(1099.84,809.84) ; v1(1604,880) R15.1@1637.01,880
  Bottom Layer w10.06: v1(1099.84,809.84) 1151.84,809.84 1219,877 1252,877 1264.02,877 1272.03,885.01 1272.03,894.05 1280.04,902.06 1304.08,902.06 1312.1,894.05 1312.1,877 1312.1,846.14 1320.11,838.13 1344.15,838.13 1352.16,846.14 1352.16,877 1352.16,894.05 1360.17,902.06 1384.21,902.06 1392.22,894.05 1392.22,885.01 1400.24,877 1432.29,877 1445,877 1511.84,877 1579,809.84 1614.84,809.84 1629.91,824.91 1629.91,854.09 v1(1604,880)
CS_B: R14.1 U2.4 | length 967.1
  Top Layer w10.06: U2.4@964.96,770.47 995.39,770.47 1000.01,765.86 1097.14,765.86 v1(1099,764) ; v1(1604,920) R14.1@1637.01,920
  Bottom Layer w10.06: v1(1099,764) 1313,764 1325.02,764 1333.03,772.01 1333.03,794.86 1341.04,802.87 1365.08,802.87 1373.1,794.86 1373.1,764 1373.1,743.95 1381.11,735.94 1405.15,735.94 1413.16,743.95 1413.16,755.99 1421.17,764 1430,764 1594.37,764 1647.84,817.48 1647.84,876.16 v1(1604,920)
CS_C: R13.1 U2.2 | length 969
  Top Layer w10.06: U2.2@964.96,731.1 978.9,731.1 992,718 v1(1100,718) ; v1(1604,960) R13.1@1637.01,960
  Bottom Layer w10.06: v1@1101,719 v1(1100,718) 1597,718 1667,788 1667,897 v1(1604,960)
EVM_DVDD: C10.1 C11.1 C12.1 C13.1 C15.1 J1.50 U1.4 U2.20 U4.4 U5.4 | length 579.5
  Top Layer w10: U5.4@590,675.59 590,691 604,705 v1(660,705) ; U4.4@590,825.59 590,841 604,855 v1(660,855) ; U1.4@590,975.59 590,991 604,1005 v1(660,1005) ; U2.20@870.48,715.36 870.48,696.52 879,688 879,666 v1(880,665) ; C15.1@1738,612.9 J1.50@1808.5,612.9 ; J1.50@1808.9,612.5 v2(1870,612.5)
  Top Layer w12: v2(1704,613) C15.1@1738,613 1738,612.9 v2(1738,579)
  Top Layer w15: v1(854,665) v1(880,665) v1(880,639)
EVM_ID_PWR: C16.1 C19.1 J1.59 R10.2 R11.2 U7.8 | length 336.5
  Top Layer w10: v2(1990.4,514.4) J1.59@2051.5,514.4 2114.6,514.4 C16.1@2115,514
  Top Layer w12: U7.8@1463.19,463.39 1463.19,470.81
  Top Layer w15: R10.2@1277,535 v2(1304,535) ; v2(1463,562) C19.1@1463,535 ; 1463.19,470.81 1463,471 C19.1@1463,535 ; v2(1490,535) C19.1@1463,535 ; R11.2@1545,475 v2(1576,475) ; C16.1@2115,514 v2(2115,542)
